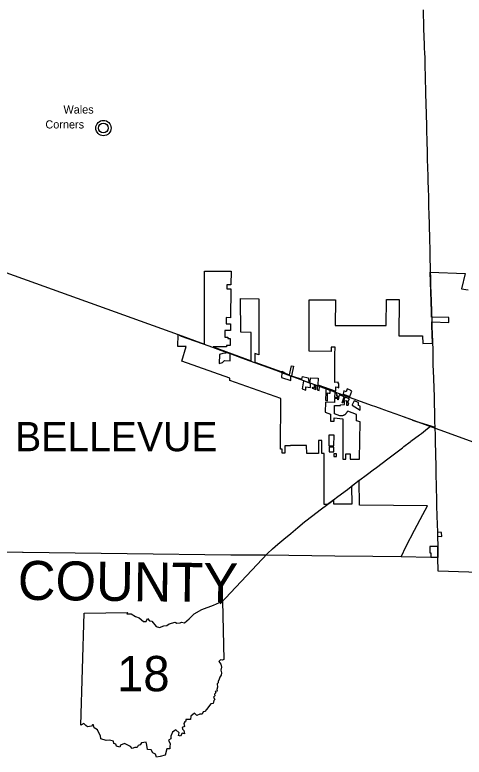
# Model space of a CAD drawing. Extents: x 0 to 798, y 0 to 440.
# Drawn here: x 507.6 to 565.2, y 100.5 to 195.7 of the extents above; entities that cross this region are included whole.
import ezdxf

# ---------------------------------------------------------------- set-up
doc = ezdxf.new("R2010")
doc.units = 0
for name, color, linetype in [('DV_X_Corp_Line', 7, 'Continuous'), ('GM_X_Adjacent_County_Text', 7, 'Continuous'), ('GM_X_Corporation_Text', 7, 'Continuous'), ('GM_X_County', 7, 'Continuous'), ('GM_X_State_Route', 7, 'Continuous'), ('GM_X_US_Route', 7, 'Continuous'), ('PV_P_Text', 7, 'Continuous')]:
    doc.layers.add(name, color=color, linetype=linetype)

msp = doc.modelspace()

# ---------------------------------------------------------------- linework, layer by layer
at = {"layer": 'DV_X_Corp_Line'}
msp.add_lwpolyline([(572.327, 124.02), (561.881, 124.384), (561.845, 126.132), (561.836, 127.549), (560.816, 127.544), (560.815, 126.733), (560.925, 126.73), (560.919, 126.141), (557.119, 126.201), (557.756, 127.568), (558.847, 129.631), (559.911, 131.627), (560.493, 132.758), (551.785, 132.821), (551.741, 135.996), (550.749, 135.244), (550.792, 132.964), (548.484, 132.987), (548.485, 133.532), (547.707, 132.937), (547.246, 132.942), (547.256, 139.442), (546.943, 139.447), (546.943, 141.116), (546.522, 141.12), (546.524, 139.446), (545.222, 139.46), (545.03, 139.462), (545.011, 140.487), (542.951, 140.476), (542.95, 140.433), (542.234, 140.439), (542.214, 139.49), (541.898, 139.498), (541.895, 139.997), (541.669, 139.999), (541.694, 146.499), (535.174, 148.839), (535.177, 149.119), (529.039, 151.317), (529.561, 153.198), (528.526, 153.194), (528.55, 154.711), (531.919, 153.489), (531.917, 162.828), (535.339, 162.829), (535.318, 161.091), (534.807, 161.08), (534.807, 160.58), (535.313, 160.574), (535.267, 156.868), (534.717, 156.887), (534.718, 156.064), (535.254, 156.069), (535.25, 155.211), (534.513, 155.221), (534.513, 154.39), (534.9, 154.39), (534.9, 154.222), (535.234, 154.222), (535.229, 153.32), (534.764, 153.32), (534.764, 153.12), (533.046, 153.119), (537.897, 151.359), (537.897, 154.977), (536.579, 155), (536.552, 159.329), (538.869, 159.288), (538.869, 152.106), (538.376, 152.285), (538.376, 151.185), (541.832, 149.931), (541.835, 150.011), (542.008, 149.945), (542.332, 149.711), (542.839, 149.528), (543.07, 150.719), (543.328, 150.659), (543.091, 149.438), (544.388, 148.97), (544.471, 149.323), (545.22, 149.175), (545.306, 148.664), (545.486, 148.603), (545.504, 149.148), (546.497, 149.116), (546.469, 148.275), (548.748, 147.435), (548.745, 148.013), (548.98, 147.953), (549.156, 147.889), (549.156, 148.437), (549.044, 148.435), (549.044, 148.585), (548.62, 148.581), (548.641, 152.139), (548.652, 153.08), (548.165, 153.076), (548.164, 152.546), (545.339, 152.59), (545.33, 159.177), (548.704, 159.177), (548.682, 155.871), (555.2, 155.868), (555.229, 159.198), (556.875, 159.183), (556.834, 154.566), (559.884, 154.534), (559.894, 153.565), (561.156, 153.589), (561.108, 154.769), (561.068, 155.784), (561.054, 156.32), (563.244, 156.253), (563.233, 156.883), (561.037, 156.955), (561.019, 157.643), (560.828, 162.72), (565.313, 162.551), (564.845, 160.574), (565.698, 160.452)], dxfattribs=at)
for points in [[(533.806, 151.004), (534.223, 151.139), (534.485, 151.402), (535.2, 151.329), (535.208, 152.228), (534.846, 152.357), (534.717, 152.36), (534.615, 152.338), (534.266, 152.263), (533.847, 152.171)], [(541.803, 149.211), (542.988, 148.807), (543.01, 149.357), (541.826, 149.788)], [(544.444, 147.738), (544.891, 147.591), (544.905, 147.998), (545.518, 147.901), (545.525, 148.441), (544.605, 148.776)], [(545.711, 147.92), (545.711, 147.856), (546.214, 147.673), (546.21, 148.195), (545.979, 148.276), (545.973, 147.839)], [(546.363, 148.142), (546.363, 147.62), (546.636, 147.544), (546.643, 148.045)], [(547.446, 146.284), (547.676, 146.192), (547.702, 147.232), (547.86, 147.18), (548.037, 147.178), (548.043, 147.525), (547.458, 147.747), (547.454, 147.303)], [(549.715, 147.078), (550.555, 146.768), (550.811, 147.452), (550.624, 147.523), (550.645, 147.581), (550.215, 147.742), (550.086, 147.364), (549.764, 147.475)], [(547.406, 144.753), (548.093, 144.514), (548.085, 143.622), (548.555, 143.618), (548.556, 144.018), (549.648, 143.896), (549.649, 138.748), (550.025, 138.748), (550.028, 139.43), (550.582, 139.428), (550.573, 138.748), (551.777, 138.749), (551.857, 143.506), (551.386, 143.666), (551.397, 144.444), (550.285, 144.896), (550.185, 144.751), (550.154, 144.702), (550.129, 144.665), (550.096, 144.622), (550.058, 144.572), (550.024, 144.533), (549.989, 144.498), (549.949, 144.463), (549.909, 144.431), (549.874, 144.407), (549.832, 144.382), (549.784, 144.356), (549.742, 144.338), (549.692, 144.318), (549.63, 144.3), (549.579, 144.289), (549.514, 144.28), (549.447, 144.276), (549.357, 144.279), (549.254, 144.296), (548.565, 144.546), (548.565, 145.601), (549.344, 145.615), (549.344, 145.717), (549.849, 145.726), (549.849, 146.232), (550.111, 146.236), (550.111, 145.673), (550.316, 145.677), (550.433, 145.896), (550.259, 145.97), (550.305, 146.084), (550.5, 146.45), (549.894, 146.703), (549.655, 145.969), (549.57, 145.967), (549.819, 146.734), (549.201, 146.993), (549.054, 146.355), (549.014, 146.362), (549.012, 146.487), (548.599, 146.51), (548.594, 145.999), (547.418, 146.022)], [(548.6, 146.656), (549.009, 146.652), (549.007, 146.799), (548.852, 146.791), (548.93, 147.106), (548.607, 147.241)], [(550.853, 145.669), (551.858, 145.026), (551.866, 145.523), (551.664, 145.603), (551.671, 146.012), (551.109, 146.203), (550.87, 145.703)], [(547.857, 141.801), (547.862, 140.461), (548.513, 140.461), (548.535, 141.801)], [(548.5, 139.661), (548.51, 140.261), (547.889, 140.261), (547.889, 139.66)], [(548.495, 139.424), (548.496, 139.089), (548.827, 139.085), (548.829, 139.437)], [(561.79, 129.359), (561.804, 128.848), (562.327, 128.842), (562.314, 129.342)]]:
    msp.add_lwpolyline(points, close=True, dxfattribs=at)
for radius in [0.982, 0.623]:
    msp.add_circle((518.971, 181.18), radius, dxfattribs=at)
at = {"layer": 'GM_X_County'}
msp.add_lwpolyline([(559.955, 196.332), (560.002, 194.034), (560.04, 192.804), (560.071, 191.986), (560.097, 191.248), (560.111, 190.992), (560.123, 190.757), (560.144, 190.224), (560.167, 189.404), (560.214, 187.517), (560.252, 185.918), (560.267, 185.344), (560.289, 184.523), (560.306, 184.031), (560.325, 183.211), (560.343, 182.596), (560.363, 181.816), (560.388, 180.544), (560.405, 179.847), (560.415, 179.396), (560.42, 179.211), (560.444, 178.371), (560.455, 177.92), (560.471, 177.428), (560.48, 177.143), (560.509, 176.119), (560.544, 175.012), (560.566, 174.152), (560.583, 173.62), (560.594, 173.17), (560.613, 172.596), (560.622, 172.145), (560.643, 171.324), (560.681, 169.889), (560.704, 169.068), (560.728, 168.127), (560.744, 167.596), (560.77, 166.57), (560.782, 165.932), (560.784, 165.873), (560.803, 164.806), (560.842, 162.96), (560.872, 161.811), (560.902, 160.909), (560.93, 160.088), (561.005, 157.769), (561.054, 156.32), (561.057, 156.201), (561.068, 155.784), (561.108, 154.769), (561.176, 152.741), (561.172, 152.659), (561.194, 151.757), (561.2, 151.524), (561.205, 150.842), (561.238, 150.006), (561.241, 149.845), (561.262, 149.3), (561.268, 148.885), (561.3, 147.995), (561.35, 146.606), (561.415, 143.971), (561.403, 143.842), (561.42, 143.505), (561.438, 142.836), (561.468, 141.741), (561.488, 141.025), (561.569, 137.753), (561.584, 137.231), (561.589, 136.518), (561.595, 135.574), (561.619, 134.78), (561.615, 134.625), (561.644, 134.045), (561.654, 133.37), (561.653, 132.786), (561.711, 131.417), (561.79, 129.359), (561.804, 128.848), (561.836, 127.549), (561.845, 126.132), (560.919, 126.141), (557.119, 126.201), (553.519, 126.265), (548.612, 126.303), (539.774, 126.416), (535.32, 126.441), (522.009, 126.601), (508.706, 126.757), (508.594, 126.756), (502.016, 126.819)], dxfattribs=at)
at = {"layer": 'GM_X_State_Route'}
msp.add_line((485.962, 170.066), (528.55, 154.711), dxfattribs=at)
for points in [[(556.268, 139.42), (557.303, 140.2), (557.483, 140.338), (558.284, 140.951), (558.32, 140.978), (558.383, 141.027), (559.46, 141.844), (559.727, 142.019), (560.235, 142.438), (560.937, 143)], [(551.794, 136.046), (551.851, 136.089), (552.649, 136.686), (553.7, 137.488), (553.794, 137.558), (554.846, 138.35), (555.263, 138.664), (556.268, 139.42)], [(548.475, 133.523), (549.006, 133.929), (550.237, 134.851), (551.383, 135.738), (551.794, 136.046)], [(547.747, 132.969), (547.876, 133.066), (548.371, 133.444)], [(548.371, 133.444), (548.475, 133.523)], [(533.924, 120.193), (539.98, 126.636), (540.626, 127.24), (541.336, 127.83), (542.107, 128.48), (542.972, 129.21), (543.898, 129.991), (544.743, 130.687), (545.804, 131.499), (546.765, 132.225), (547.747, 132.969)]]:
    msp.add_lwpolyline(points, dxfattribs=at)
at = {"layer": 'GM_X_US_Route'}
for points in [[(528.674, 154.61), (528.926, 154.52)], [(528.926, 154.52), (532.461, 153.252), (534.78, 152.42), (534.836, 152.4), (535.089, 152.309), (535.089, 152.309)], [(535.089, 152.309), (535.215, 152.264), (536.675, 151.731)], [(536.675, 151.731), (541.051, 150.133), (541.056, 150.131)], [(541.056, 150.131), (542.395, 149.642)], [(542.395, 149.642), (548.602, 147.375), (552.014, 146.139)], [(552.014, 146.139), (553.297, 145.674), (553.847, 145.475), (554.635, 145.189), (554.85, 145.11), (557.036, 144.316), (557.239, 144.243), (582.349, 135.131)], [(557.374, 144.194), (558.562, 143.763), (558.593, 143.752)], [(558.593, 143.752), (559.078, 143.575), (560.937, 143)], [(560.937, 143), (561.438, 142.836)]]:
    msp.add_lwpolyline(points, dxfattribs=at)
at = {"layer": 'PV_P_Text'}
msp.add_line((516.092, 104.645), (516.494, 119.008), dxfattribs=at)
msp.add_line((516.092, 104.645), (516.494, 119.008), dxfattribs=at)
for points in [[(516.494, 119.008), (522.067, 119.102), (521.98, 118.928), (522.506, 118.891), (523.064, 118.585), (523.536, 118.391), (524.114, 117.934), (524.46, 117.939), (524.606, 118.314), (524.871, 118.025), (525.185, 117.973), (525.728, 117.286), (526.177, 117.137), (526.714, 117.372), (527.116, 117.411), (527.409, 117.644), (528.174, 117.843), (528.387, 117.724), (528.792, 117.748), (528.995, 117.836), (529.349, 117.757), (529.97, 118.279), (530.61, 118.895), (531.594, 119.476), (533.064, 120.027), (534.227, 120.519), (534.395, 113.066)], [(516.494, 119.008), (522.067, 119.102), (521.98, 118.928), (522.506, 118.891), (523.064, 118.585), (523.536, 118.391), (524.114, 117.934), (524.46, 117.939), (524.606, 118.314), (524.871, 118.025), (525.185, 117.973), (525.728, 117.286), (526.177, 117.137), (526.714, 117.372), (527.116, 117.411), (527.409, 117.644), (528.174, 117.843), (528.387, 117.724), (528.792, 117.748), (528.995, 117.836), (529.349, 117.757), (529.97, 118.279), (530.61, 118.895), (531.594, 119.476), (533.064, 120.027), (534.227, 120.519), (534.395, 113.066)], [(534.395, 113.066), (534.223, 112.961), (533.956, 113.01), (533.776, 112.801), (533.999, 112.452), (534.104, 112.084), (534.011, 111.678), (534.102, 111.343), (534.04, 111.062), (533.872, 110.783), (533.814, 110.517), (533.672, 110.237), (533.683, 110.08), (533.547, 109.956), (533.572, 109.49), (533.503, 109.231), (533.527, 109.009), (533.306, 108.95), (533.357, 108.766), (533.216, 108.624), (533.246, 108.379), (533.087, 108.223), (533.242, 107.91), (533.118, 107.811), (533.015, 107.431), (532.732, 107.354), (532.165, 106.658), (531.965, 106.395), (531.74, 106.33), (531.616, 106.06), (531.34, 106.059), (530.921, 105.872), (530.651, 106.194), (530.177, 105.806), (530.122, 105.358), (529.522, 105.372), (529.546, 105.146), (529.412, 105.08), (529.29, 104.853), (529.361, 104.45), (529.08, 104.347), (529.114, 104.113), (529.294, 103.97), (529.374, 103.523), (529.076, 103.614), (528.831, 103.237), (528.58, 103.325), (528.662, 103.644), (528.238, 104.028), (527.836, 103.721), (527.627, 103.229), (527.624, 102.899), (527.325, 102.699), (527.517, 102.232), (527.482, 101.91), (527.488, 101.605), (527.114, 101.615), (526.887, 100.791)], [(534.395, 113.066), (534.223, 112.961), (533.956, 113.01), (533.776, 112.801), (533.999, 112.452), (534.104, 112.084), (534.011, 111.678), (534.102, 111.343), (534.04, 111.062), (533.872, 110.783), (533.814, 110.517), (533.672, 110.237), (533.683, 110.08), (533.547, 109.956), (533.572, 109.49), (533.503, 109.231), (533.527, 109.009), (533.306, 108.95), (533.357, 108.766), (533.216, 108.624), (533.246, 108.379), (533.087, 108.223), (533.242, 107.91), (533.118, 107.811), (533.015, 107.431), (532.732, 107.354), (532.165, 106.658), (531.965, 106.395), (531.74, 106.33), (531.616, 106.06), (531.34, 106.059), (530.921, 105.872), (530.651, 106.194), (530.177, 105.806), (530.122, 105.358), (529.522, 105.372), (529.546, 105.146), (529.412, 105.08), (529.29, 104.853), (529.361, 104.45), (529.08, 104.347), (529.114, 104.113), (529.294, 103.97), (529.374, 103.523), (529.076, 103.614), (528.831, 103.237), (528.58, 103.325), (528.662, 103.644), (528.238, 104.028), (527.836, 103.721), (527.627, 103.229), (527.624, 102.899), (527.325, 102.699), (527.517, 102.232), (527.482, 101.91), (527.488, 101.605), (527.114, 101.615), (526.887, 100.791)], [(526.887, 100.791), (526.237, 100.633), (525.785, 100.539), (525.626, 100.913), (525.303, 101.111), (525.093, 101.488), (524.63, 101.539), (524.52, 102.057), (524.468, 102.478), (523.834, 102.374), (523.66, 102.117), (523.435, 102.048), (523.305, 101.789), (522.998, 101.767), (522.67, 101.645), (522.455, 101.899), (521.916, 102.154), (521.674, 102.286), (521.167, 102.081), (521.059, 101.839), (520.656, 101.946), (520.562, 102.216), (520.317, 102.297), (520.264, 102.583), (519.742, 102.735), (519.343, 102.675), (518.64, 102.905), (518.597, 103.281), (518.357, 103.74), (518.232, 104.058), (517.788, 104.301), (517.698, 104.68), (517.555, 104.669), (517.425, 104.515), (516.931, 104.445), (516.734, 104.599), (516.458, 104.864), (516.092, 104.645)], [(526.887, 100.791), (526.237, 100.633), (525.785, 100.539), (525.626, 100.913), (525.303, 101.111), (525.093, 101.488), (524.63, 101.539), (524.52, 102.057), (524.468, 102.478), (523.834, 102.374), (523.66, 102.117), (523.435, 102.048), (523.305, 101.789), (522.998, 101.767), (522.67, 101.645), (522.455, 101.899), (521.916, 102.154), (521.674, 102.286), (521.167, 102.081), (521.059, 101.839), (520.656, 101.946), (520.562, 102.216), (520.317, 102.297), (520.264, 102.583), (519.742, 102.735), (519.343, 102.675), (518.64, 102.905), (518.597, 103.281), (518.357, 103.74), (518.232, 104.058), (517.788, 104.301), (517.698, 104.68), (517.555, 104.669), (517.425, 104.515), (516.931, 104.445), (516.734, 104.599), (516.458, 104.864), (516.092, 104.645)]]:
    msp.add_lwpolyline(points, dxfattribs=at)

# ---------------------------------------------------------------- texts
at = {"layer": 'DV_X_Corp_Line'}
for s, p in [('Wales', (513.85, 183.035)), ('Corners', (511.537, 181.125))]:
    msp.add_text(s, height=1.0417, rotation=0.00001, dxfattribs=at).set_placement(p)
at = {"layer": 'GM_X_Adjacent_County_Text'}
msp.add_text('SENECA COUNTY', height=5, rotation=359.30548, dxfattribs=at).set_placement((478.623, 121.073))
at = {"layer": 'GM_X_Corporation_Text'}
msp.add_text('BELLEVUE', height=3.75, rotation=0.00001, dxfattribs=at).set_placement((507.657, 139.749))
at = {"layer": 'PV_P_Text'}
msp.add_text('18', height=4.5281, dxfattribs=at).set_placement((520.718, 108.983))

doc.saveas('drawing.dxf')
